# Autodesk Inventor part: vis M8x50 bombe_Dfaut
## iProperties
Created: 2006-03
Part Number: vis M8x50 bombe_Dfaut
Document SubType Name: Modeling
Designer: Flavien MARTY
Author: Flavien MARTY
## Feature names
1. Base1
